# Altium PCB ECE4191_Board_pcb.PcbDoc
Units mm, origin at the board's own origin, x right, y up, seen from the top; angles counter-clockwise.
Board outline 150 x 61 mm, 2 copper layers (Top Layer, Bottom Layer), stack 1.65 mm thick; 23 components, 41 nets, 136 pads, 41 vias.
Unrouted connection lines stored in the file: 1.
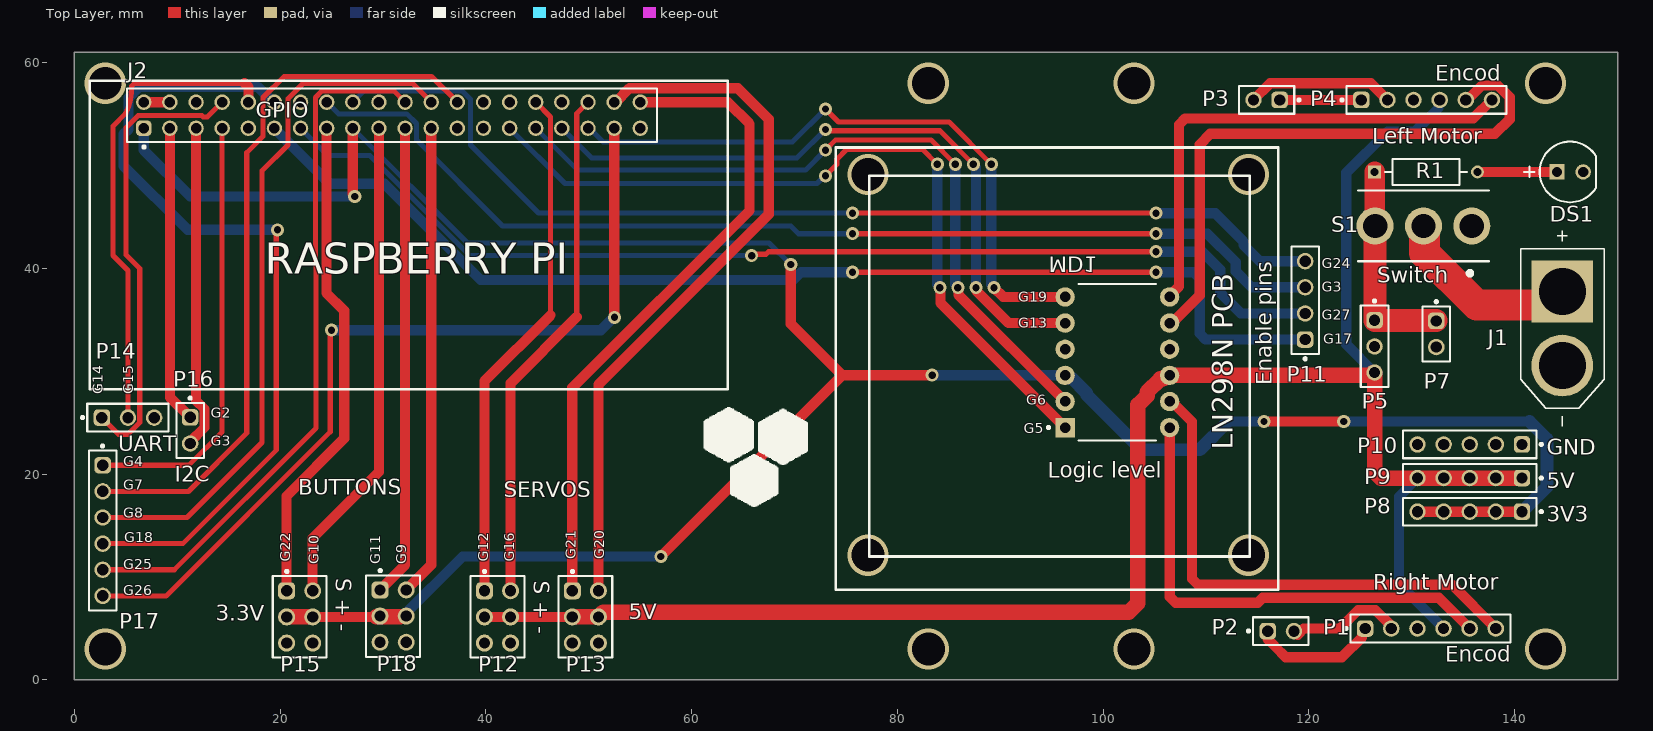
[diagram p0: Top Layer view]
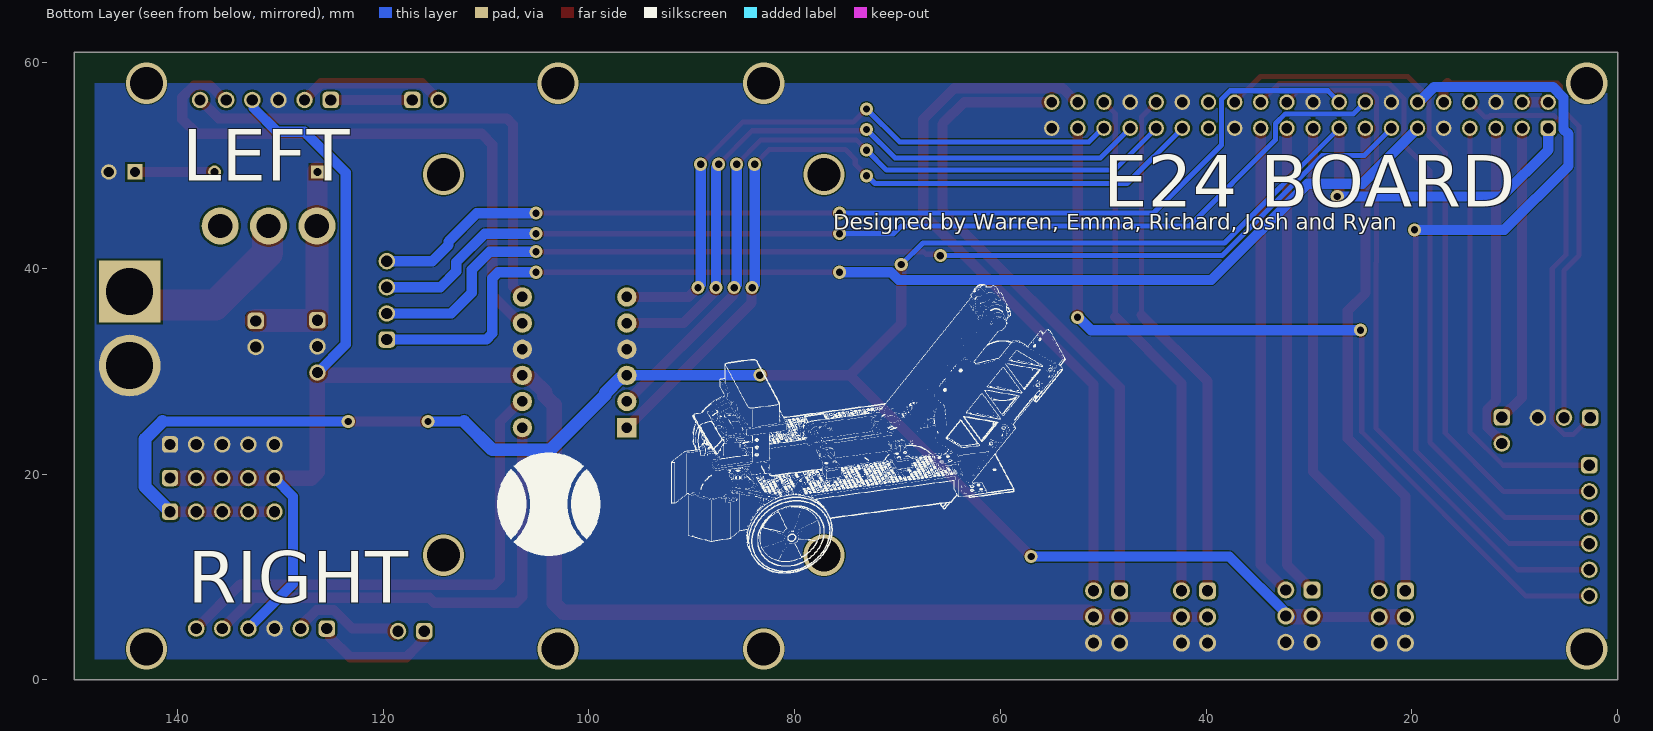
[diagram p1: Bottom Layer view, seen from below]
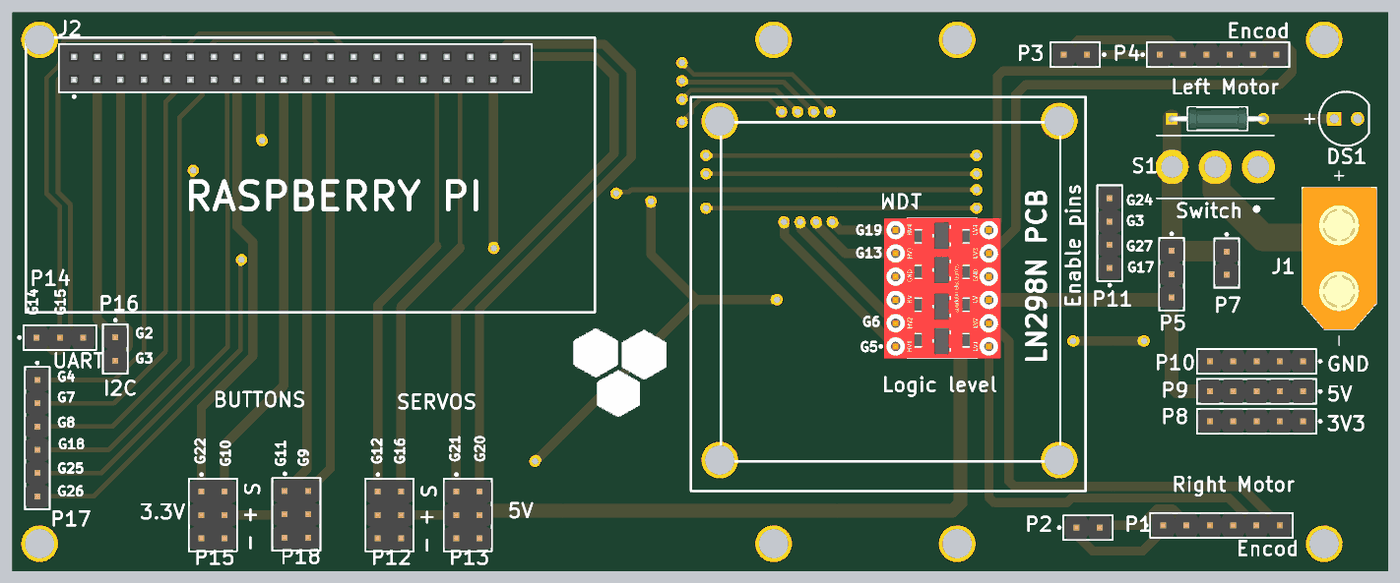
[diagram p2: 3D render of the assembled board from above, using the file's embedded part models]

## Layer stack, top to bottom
Top Solder: solder mask 0.0127, Solder Resist, Dk 3.8
Top Layer: signal copper 0.075
Dielectric: core 1.5, FR-4, Dk 4.5
Bottom Layer: signal copper 0.075
Bottom Solder: solder mask 0.0127, Solder Resist, Dk 3.8

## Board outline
0,0 0,61 150,61 150,0

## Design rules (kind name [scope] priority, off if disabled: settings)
BoardOutlineClearance [All] p1: gap=0.2 ignorepadtopadclearanceinfootprint=FALSE
Clearance [All] p1: gap=0.1 ignorepadtopadclearanceinfootprint=FALSE except(0.2: Arc-Arc Arc-Track Track-Track THPad-Fill THPad-Poly THPad-Region; 0.5: Arc-SMDPad Arc-Text Track-SMDPad Track-Text SMDPad-SMDPad SMDPad-THPad SMDPad-Via SMDPad-Fill SMDPad-Poly SMDPad-Region SMDPad-Text SMDPad-Hole THPad-THPad THPad-Via THPad-Text THPad-Hole Via-Text Fill-Text Poly-Text Region-Text Text-Text Text-Hole)
ComponentClearance [All] p1: gap=0.127 collisioncheckmode=3 verticalgap=0.127 showdistances=TRUE
DiffPairsRouting [All] p1: maxlimit=0.254 minlimit=0.127 mostfreqgap=0.127 toplayer_minwidth=0.127 toplayer_maxwidth=25.4 toplayer_prefwidth=0.127 bottomlayer_minwidth=0.127 bottomlayer_maxwidth=25.4 bottomlayer_prefwidth=0.127 maxuncoupledlength=12.7
Height [All] p1: minheight=0 maxheight=1816.048 prefheight=12.7
HoleSize [All] p1: absolutevalues=TRUE maxlimit=6.3 minlimit=0.3 maxpercent=80.000 minpercent=20.000
HoleToHoleClearance [All] p1: gap=0.25 allowstackedmicrovias=FALSE
MinimumAnnularRing [All] p1: minimumring=0.076
MinimumSolderMaskSliver [All] p1: minsoldermaskwidth=0
PlaneClearance [All] p1: clearance=0.127
PlaneConnect PlaneConnectPowerPads [InPadClass('PowerPads')] p1: planeconnectstyle=Direct reliefexpansion=0.508 reliefentries=4 reliefconductorwidth=0.254 reliefairgap=0.254
PlaneConnect [All] p2: pad.planeconnectstyle=Relief pad.reliefexpansion=0.3 pad.reliefentries=4 pad.reliefconductorwidth=0.127 pad.reliefairgap=0.127 via.planeconnectstyle=Direct via.reliefexpansion=0.3 via.reliefentries=4 via.reliefconductorwidth=0.127 via.reliefairgap=0.127
PolygonConnect PolygonConnectPowerPads [All vs (InPadClass('PowerPads'))] p1: connectstyle=Direct reliefconductorwidth=0.254 reliefentries=4 polygonreliefangle="90 Angle" airgapwidth=0.254
PolygonConnect [All] p2: thpad.connectstyle=Direct thpad.reliefconductorwidth=0.127 thpad.reliefentries=4 thpad.polygonreliefangle="90 Angle" thpad.airgapwidth=0.127 smdpad.connectstyle=Relief smdpad.reliefconductorwidth=0.127 smdpad.reliefentries=4 smdpad.polygonreliefangle="90 Angle" smdpad.airgapwidth=0.127 via.connectstyle=Direct via.reliefconductorwidth=0.127 via.reliefentries=4 via.polygonreliefangle="90 Angle" via.airgapwidth=0.127
RoutingVias [All] p1: holewidth=0.3 width=0.6 viastyle="Through Hole" minholewidth=0.3 minwidth=0.6 maxholewidth=0.6 maxwidth=6.6
SilkToSilkClearance [All] p1: silktosilkclearance=0
SilkToSolderMaskClearance [IsPad] p1: minsilkscreentomaskgap=0.127 clearancetoexposedcopper=TRUE
SolderMaskExpansion [All] p1: expansion=0.075 istentingtop=FALSE
Width [All] p1: maxlimit=25.4 minlimit=0.1 preferedwidth=1 minimp=50.000000 maximp=50.000000 favimp=50.000000
20 further rules are at their usual default settings.

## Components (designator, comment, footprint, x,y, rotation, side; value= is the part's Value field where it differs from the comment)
DS1 "UR502DC" CGX-UR502DC 145.377,49.377 r0 top
J1 "XT60-M" AMASS_XT60-M 144.627,34.155 r270 top
J2 "GPIO" 61304021821 30.875,54.895 r0 top
MD1 "BOB-12009" FP-BOB-12009-MFG 101.377,30.877 r0 top
P1 "Motor L" 61300611121 131.81,5 r0 top
P2 "LMotor Drive" 61300211121 117.27,4.75 r0 top
P3 "RMotor Drive" 61300211121 115.877,56.377 r180 top
P4 "Motor R" 61300611121 131.437,56.377 r0 top
P5 "LN298N" 61300311121 126.377,32.417 r270 top
P7 "To buck convter" 61300211121 132.377,33.627 r270 top
P8 "3.3V rail" 61300511121 135.627,16.36 r180 top
P9 "5V rail" 61300511121 135.627,19.627 r180 top
P10 "GND rail" 61300511121 135.627,22.894 r180 top
P11 "Motor enable pins" 61300411121 119.627,36.897 r90 top
P12 "61300621121" 61300621121 41.127,6.127 r270 top
P13 "61300621121" 61300621121 49.668,6.127 r270 top
P14 "UART" 61300311121 5.21,25.5 r0 top
P15 "61300621121" 61300621121 21.897,6.127 r270 top
P16 "I2C" 61300211121 11.25,24.25 r270 top
P17 "Spare pins" 61300611121 2.75,14.52 r270 top
P18 "61300621121" 61300621121 30.98,6.21 r270 top
R1 "1K" FP-MRS25-MFG 131.377,49.377 r0 top
S1 "Power Switch" 1MS1T1B1M1QES-1 131.127,44.127 r90 top

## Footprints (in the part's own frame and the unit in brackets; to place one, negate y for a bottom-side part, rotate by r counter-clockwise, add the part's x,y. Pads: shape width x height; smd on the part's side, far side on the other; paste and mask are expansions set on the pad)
1MS1T1B1M1QES-1 [mm]
  round 3.6 hole 2.37: 1(0,-4.7) 2(0,0) 3(0,4.7)
  silkscreen extent -4.76,-6.35 3.43,6.35
61300211121 [mm] "Pin Header, pitch 2.54 mm, THT, Vertical, single row, 2p"
  rrect50% 1.6x1.6 hole 1.1: 1(-1.27,0)
  round 1.6 hole 1.1: 2(1.27,0)
  silkscreen extent -3.26,-1.35 2.69,1.35, body extent -2.54,-1.27 2.54,1.27, height 8.57
61300311121 [mm] "Pin Header, pitch 2.54 mm, THT, Vertical, single row, 3p"
  rrect50% 1.6x1.6 hole 1.1: 1(-2.54,0)
  round 1.6 hole 1.1: 2(0,0) 3(2.54,0)
  silkscreen extent -4.53,-1.35 3.96,1.35, body extent -3.81,-1.27 3.81,1.27, height 8.57
61300411121 [mm] "Pin Header, pitch 2.54 mm, THT, Vertical, single row, 4p"
  rrect50% 1.6x1.6 hole 1.1: 1(-3.81,0)
  round 1.6 hole 1.1: 2(-1.27,0) 3(1.27,0) 4(3.81,0)
  silkscreen extent -5.8,-1.35 5.23,1.35, body extent -5.08,-1.27 5.08,1.27, height 8.57
61300511121 [mm] "Pin Header, pitch 2.54 mm, THT, Vertical, single row, 5p"
  rrect50% 1.6x1.6 hole 1.1: 1(-5.08,0)
  round 1.6 hole 1.1: 2(-2.54,0) 3(0,0) 4(2.54,0) 5(5.08,0)
  silkscreen extent -7.07,-1.35 6.5,1.35, body extent -6.35,-1.27 6.35,1.27, height 8.57
61300611121 [mm] "Pin Header, pitch 2.54 mm, THT, Vertical, single row, 6p"
  rrect50% 1.6x1.6 hole 1.1: 1(-6.35,0)
  round 1.6 hole 1.1: 2(-3.81,0) 3(-1.27,0) 4(1.27,0) 5(3.81,0) 6(6.35,0)
  silkscreen extent -8.34,-1.35 7.77,1.35, body extent -7.62,-1.27 7.62,1.27, height 8.57
61300621121 [mm] "Pin Header, pitch 2.54 mm, THT, Vertical, dual row, 6p"
  rrect50% 1.65x1.65 hole 1.1: 1(-2.54,-1.27)
  round 1.65 hole 1.1: 2(-2.54,1.27) 3(0,-1.27) 4(0,1.27) 5(2.54,-1.27) 6(2.54,1.27)
  silkscreen extent -4.54,-2.62 3.96,2.62, body extent -3.81,-2.54 3.81,2.54, height 8.59
61304021821 [mm] "Socket Header, Pitch 2.54 mm, THT, Vertical, dual row, 40p"
  rrect50% 1.5x1.5 hole 1.02: 1(-24.13,-1.27)
  round 1.5 hole 1.02: 2(-24.13,1.27) 3(-21.59,-1.27) 4(-21.59,1.27) 5(-19.05,-1.27) 6(-19.05,1.27) 7(-16.51,-1.27) 8(-16.51,1.27) 9(-13.97,-1.27) 10(-13.97,1.27) 11(-11.43,-1.27) 12(-11.43,1.27) 13(-8.89,-1.27) 14(-8.89,1.27) 15(-6.35,-1.27) 16(-6.35,1.27) 17(-3.81,-1.27) 18(-3.81,1.27) 19(-1.27,-1.27) 20(-1.27,1.27) 21(1.27,-1.27) 22(1.27,1.27) 23(3.81,-1.27) 24(3.81,1.27) 25(6.35,-1.27) 26(6.35,1.27) 27(8.89,-1.27) 28(8.89,1.27) 29(11.43,-1.27) 30(11.43,1.27) 31(13.97,-1.27) 32(13.97,1.27) 33(16.51,-1.27) 34(16.51,1.27) 35(19.05,-1.27) 36(19.05,1.27) 37(21.59,-1.27) 38(21.59,1.27) 39(24.13,-1.27) 40(24.13,1.27)
  silkscreen extent -25.78,-3.22 25.78,2.62, body extent -25.65,-2.54 25.65,2.54, height 8.45
AMASS_XT60-M [mm]
  round 6 hole 4.55: N(3.6,0)
  rect 6x6 / inner round 6 / far side rect 6x6 hole 4.55: P(-3.6,0)
  silkscreen extent -9.5,-4.05 9.5,4.05, body extent -7.75,-4.05 7.75,4.05, height 16
CGX-UR502DC [mm] "THD, 2-Leads, Dia 5.9mm, Pin Spacing 2.54mm"
  rect 1.5x1.5 hole 1: 1(-1.27,0)
  round 1.5 hole 1: 2(1.27,0)
  silkscreen extent -4.47,-2.95 2.5,2.95, body extent -2.95,-2.95 2.5,2.95, height 9.1
FP-BOB-12009-MFG [mm]
  rect 1.88x1.88 hole 1.02 paste-2539.97 mask+0: 1(-5.08,-6.35)
  round 1.88 hole 1.02 paste-2539.97 mask+0: 2(-5.08,-3.81) 3(-5.08,-1.27) 4(-5.08,1.27) 5(-5.08,3.81) 6(-5.08,6.35) 7(5.08,6.35) 8(5.08,3.81) 9(5.08,1.27) 10(5.08,-1.27) 11(5.08,-3.81) 12(5.08,-6.35)
  silkscreen extent -6.82,-7.62 3.76,7.62, body extent -6.35,-7.62 6.35,7.62, height 5.34
FP-MRS25-MFG [mm]
  rect 1.25x1.25 hole 0.75 paste-2539.97 mask+0: 1(-5,0)
  round 1.25 hole 0.75 paste-2539.97 mask+0: 2(5,0)
  silkscreen extent -3.98,-1.25 3.98,1.25, body extent -5.72,-1.35 5.72,1.35, height 0.25

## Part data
DS1: library part CMP-007-00009-1, "Red LED, 80 mW, 30 mA, -25 to 85 degC, 2-Pin THD", Manufacturer="Shenzhen CGX", Package Description="2-Pin Through Hole Device, Dia 5.9 mm, Height 9.1 mm", Power=80mW
J1: "Plug; DC supply; XT60; male; PIN: 2; for cable; soldered; 30A; 500V", Package=Package
J2: library part CMP-1502-01370-3, Contact Resistance=20mΩ, Current Rating=3A, Operating Supply Voltage=250V
MD1: library part CMP-157458-000001-1, "LOGIC LEVEL CONVERTER - BI-DIREC"
P1 P4 P17: library part CMP-1502-01070-3, Color=Black, Contact Resistance=20mΩ, Current Rating=3A, Max Operating Temperature=105°C, Min Operating Temperature=-40°C, Operating Supply Voltage=250V
P2 P3 P7 P16: library part CMP-1712-00002-6, Color=Black, Contact Resistance=20mΩ, Current Rating=3A, Max Operating Temperature=125°C, Min Operating Temperature=-40°C, Operating Supply Voltage=250V
P5 P14: library part CMP-1502-01062-3, Color=Black, Contact Resistance=20mΩ, Current Rating=3A, Max Operating Temperature=105°C, Min Operating Temperature=-40°C, Operating Supply Voltage=250V
P8 P9 P10: library part CMP-1502-01068-3, Color=Black, Contact Resistance=20mΩ, Current Rating=3A, Max Operating Temperature=105°C, Min Operating Temperature=-40°C, Operating Supply Voltage=250V
P11: library part CMP-1502-01064-3, Color=Black, Contact Resistance=20mΩ, Current Rating=3A, Max Operating Temperature=105°C, Min Operating Temperature=-40°C, Operating Supply Voltage=250V
P12 P13 P15 P18: library part CMP-1502-01072-3, Color=Black, Contact Resistance=20mΩ, Current Rating=3A, Max Operating Temperature=105°C, Min Operating Temperature=-40°C, Operating Supply Voltage=250V
R1: library part CMP-00030-42632392-1, "1K resistor", Case/Package=Conformal, Max Operating Temperature=155°C, Max Power Dissipation=600mW, Min Operating Temperature=-55°C, Resistance=10kΩ, Temperature Coefficient=50ppm/°C, Tolerance=1%, Voltage Rating=350V
S1: library part 1MS1T1B1M1QES-1, "Switch", Manufacturer_Name="RS Pro"

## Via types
v1: diameter 1.27, hole 0.711, Top Layer to Bottom Layer, 29 vias
v2: diameter 4, hole 3.2, Top Layer to Bottom Layer, 12 vias

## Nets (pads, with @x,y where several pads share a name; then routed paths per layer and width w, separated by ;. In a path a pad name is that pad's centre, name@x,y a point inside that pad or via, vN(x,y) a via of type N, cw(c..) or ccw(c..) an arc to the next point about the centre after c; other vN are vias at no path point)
3.3V: J2.1 J2.17 MD1.3 P8.1 P8.2 P8.3 P8.4 P8.5 P15.3 P15.4 P18.3 P18.4 | length 247.5
  Top Layer w1: J2.1@6.62,53.5 J2.1 J2.1@6.87,53.75 ; P15.4 P18.3@29.337,6.127 ; J2.17 27.065,47.258 27.25,47.073 v1(27.25,47) ; v1(57,12) 74.627,29.627 ; v1@69.627,40.304 69.627,34.627 74.627,29.627 ; v1(83.377,29.627) 74.627,29.627 ; v1(115.627,25.127) v1(123.377,25.127) ; P8.5 P8.4 P8.3 P8.2 P8.1
  Top Layer w1.5: P15.3@20.587,6.127 P15.3 P15.4@23.127,6.127 ; P18.3@29.337,6.127 P18.4@31.667,6.127
  Bottom Layer w0.5: J2.17 38.213,42.477 67.527,42.477 v1(69.627,40.377)
  Bottom Layer w1: J2.1 6.745,51.505 11.25,47 v1(27.25,47) ; P18.4@31.877,6.127 37.75,12 v1(57,12) ; v1(83.377,29.627) 83.397,29.607 MD1.3 ; 112.127,25.127 v1(115.627,25.127) ; v1(123.377,25.127) 141.431,25.127
  Bottom Layer w1.25: MD1.3 96.467,29.607 96.782,29.292 96.992,29.292 98.362,27.922 98.362,27.746 103.731,22.377 109.377,22.377 112.127,25.127 ; P8.1 143.127,18.78 143.127,23.431 141.431,25.127
"12V original": J1.P S1.2 | length 18.7
  Top Layer w3: S1.2 131.242,44.012 131.242,41.512 136.308,36.446 143.318,36.446 J1.P
+5: MD1.10 P1.4 P4.4 P5.3 P9.1 P9.2 P9.3 P9.4 P9.5 P12.3 P12.4 P13.3 P13.4 | length 182.2
  Top Layer w1: P12.3 P12.4 P13.3
  Top Layer w1.5: P13.3 P13.4 51.403,6.592 102.498,6.592 103.377,7.471 103.377,26.731 104.267,27.621 104.267,27.974 105.55,29.257 105.838,29.257 105.998,29.417 106.164,29.417 106.354,29.607 125.945,29.607 126.215,29.877 P5.3 126.377,20.213 126.963,19.627 P9.5 P9.4 P9.3 P9.2 P9.1
  Bottom Layer w1: P5.3 126.371,29.877 123.627,32.621 123.627,49.291 127.633,53.297 130.297,53.297 132.592,55.592 132.592,56.262 P4.4 ; P9.5 128.747,17.827 128.747,9.333 P1.4 P1.4@133.08,5.006
+12: P5.1 P7.1 R1.1 S1.3 | length 20.5
  Top Layer w2: R1.1 126.402,49.352 126.402,44.152 S1.3 S1.3@126.402,44.102 ; P5.1@126.402,34.982 P5.1 P5.1@126.407,34.927 ; P7.1@132.347,34.927 P7.1
  Top Layer w2.25: P5.1@126.402,34.982 S1.3@126.402,44.102 ; P5.1@126.407,34.927 P7.1@132.347,34.927
GND: DS1.2 J1.N J2.6 J2.9 J2.14 J2.20 J2.25 J2.30 J2.34 J2.39 MD1.4 MD1.9 P1.3 P4.3 P5.2 P7.2 P10.1 P10.2 P10.3 P10.4 P10.5 P12.5 P12.6 P13.5 P13.6 P14.3 P15.5 P15.6 P18.5 P18.6
GPIO22: J2.15 P15.1 | length 48
  Top Layer w1: P15.1 20.627,17.877 26.235,23.485 26.235,35.875 24.5,37.61 24.5,53.6 J2.15
"GPIO 2 (SDA)": J2.3 P16.1 | length 28.9
  Top Layer w1: J2.3 9.285,27.485 P16.1
"GPIO 3 (SCL)": J2.5 P16.2 | length 31.6
  Top Layer w1: P16.2 11.25,23.142 12.65,24.542 12.65,26.334 11.825,27.159 J2.5
"GPIO 4": J2.7 P17.1 | length 42.5
  Top Layer w0.5: P17.1 11.12,20.87 14.365,24.115 J2.7
"GPIO 5": J2.29 MD1.1 | length 76.8
  Top Layer w0.5: v1(73,49) 74.099,50.099 74.099,50.599 75.05,51.55 82.454,51.55 v1(83.877,50.127)
  Top Layer w1: v1(84.127,38.127) 84.179,38.075 84.179,36.645 MD1.1
  Bottom Layer w0.5: J2.29 47.68,48.25 72.177,48.25 72.927,49 v1(73,49)
  Bottom Layer w1: v1(83.877,50.127) 83.877,38.45 84.127,38.2 v1(84.127,38.127)
"GPIO 6": J2.31 MD1.2 | length 72.2
  Top Layer w0.5: v1(73,51.5) 74,52.5 83.254,52.5 v1(85.627,50.127)
  Top Layer w1: v1(85.877,38.127) 85.929,38.075 85.929,37.435 MD1.2
  Bottom Layer w0.5: J2.31 48.92,49.55 71.05,49.55 v1(73,51.5)
  Bottom Layer w1: v1(85.627,50.127) 85.627,38.45 85.877,38.2 v1(85.877,38.127)
"GPIO 7": J2.26 P17.2 | length 70.4
  Top Layer w0.5: P17.2 11.08,18.33 16.75,24 16.75,51.25 18.345,52.845 18.345,56.621 20.389,58.665 34.725,58.665 J2.26
"GPIO 8": J2.24 P17.3 | length 68.3
  Top Layer w0.5: P17.3 10.96,15.79 18.25,23.08 18.25,49.5 20.75,52 20.75,56.486 22.229,57.965 32.885,57.965 J2.24
"GPIO 9 (MISO)": J2.21 P18.1 | length 45.9
  Top Layer w1: P18.1 32.145,11.185 J2.21
"GPIO 10(MOSI)": J2.19 P15.2 | length 47.6
  Top Layer w1: P15.2 23.167,8.947 23.147,8.967 23.147,13.78 29.605,20.238 J2.19
"GPIO 11": J2.23 P18.2 | length 45.9
  Top Layer w1: P18.2 34.685,11.185 J2.23
"GPIO 12": J2.32 P12.1 | length 50.8
  Top Layer w0.5: J2.32 46.285,54.725 46.285,35.465
  Top Layer w1: P12.1 39.857,29.037 46.285,35.465
"GPIO 13": J2.33 MD1.5 | length 66.1
  Top Layer w0.5: v1(73,53.5) 73.123,53.377 84.127,53.377 v1(87.377,50.127)
  Top Layer w1: v1(87.627,38.127) 87.679,38.075 87.679,37.825 90.817,34.687 MD1.5
  Bottom Layer w0.5: J2.33 50.26,50.75 70.25,50.75 v1(73,53.5)
  Bottom Layer w1: v1(87.377,50.127) 87.377,50.054 87.627,49.804 v1(87.627,38.127)
"GPIO 14 (TXD)": J2.8 P14.1 | length 44.7
  Top Layer w0.5: P14.1 4.31,23.86 5.197,23.86 6.36,25.024 6.36,39.987 5.017,41.33 5.017,53.672 6.195,54.85 12.406,54.85 12.521,54.735 12.935,54.735 J2.8@14.49,56.29
"GPIO 15 (RXD)": J2.10 P14.2 | length 46.4
  Top Layer w0.5: P14.2 5.21,39.79 3.75,41.25 3.75,53.827 5,55.077 ccw(c-0.183,57.537) 5.5,56.75 ccw(c0.619,57.426) 5.547,57.426 5.547,57.707 5.839,58 16.539,58
  Top Layer w1: 16.539,58 16.934,57.604 16.934,56.386 J2.10@17.03,56.29
"GPIO 16": J2.36 P12.2 | length 50.6
  Top Layer w0.5: 48.825,35.288 48.825,55.065 J2.36
  Top Layer w1: P12.2 42.397,28.86 48.825,35.288
"GPIO 17": J2.11 P11.1 | length 112.5
  Top Layer w0.5: v1(75.627,39.627) v1(105.127,39.627)
  Bottom Layer w1: J2.11 24.835,48.235 30.122,48.235 39.48,38.877 69.874,38.877 70.624,39.627 v1(75.627,39.627) ; v1(105.127,39.627) 108.791,39.627 109.377,39.041 109.377,33.673 109.963,33.087 P11.1
"GPIO 18": J2.12 P17.4 | length 81.7
  Top Layer w0.5: P17.4 10.54,13.25 19.627,22.337 19.627,43.627 v1(19.75,43.75)
  Bottom Layer w1: J2.12 19.31,56.165 17.835,57.64 6.311,57.64 5.265,56.594 5.265,53.541 4.767,53.043 4.767,49.99 11.007,43.75 v1(19.75,43.75)
"GPIO 19": J2.35 MD1.6 | length 62.7
  Top Layer w0.5: v1(73,55.5) 74.273,54.227 85.027,54.227 v1(89.127,50.127)
  Top Layer w1: v1(89.377,38.127) 90.277,37.227 MD1.6
  Bottom Layer w0.5: J2.35 50.06,53.625 51.41,52.275 69.775,52.275 v1(73,55.5)
  Bottom Layer w1: v1(89.127,50.127) 89.127,38.45 89.377,38.2 v1(89.377,38.127)
"GPIO 20": J2.38 P13.2 | length 69.5
  Top Layer w1: P13.2 50.938,28.688 67.5,45.25 67.5,54.5 64.485,57.515 53.95,57.515 52.6,56.165 J2.38
"GPIO 21": J2.40 P13.1 | length 64
  Top Layer w1: P13.1 48.398,28.398 65.627,45.627 65.627,54.046 63.508,56.165 J2.40
"GPIO 23": J2.16 P11.3 | length 104
  Top Layer w0.5: v1(75.627,43.377) v1(105.127,43.377)
  Bottom Layer w0.5: J2.16 25.663,55.027 32.298,55.027 33.25,54.076 33.25,52.5 41.623,44.127 69.627,44.127 70.377,43.377 v1(75.627,43.377)
  Bottom Layer w1: v1(105.127,43.377) 110.127,43.377 112.877,40.627 112.877,39.707 114.417,38.167 P11.3
"GPIO 24": J2.18 P11.4 | length 102.7
  Top Layer w0.5: v1(75.627,45.377) v1(105.127,45.377)
  Bottom Layer w0.5: J2.18 28.165,57.265 37.681,57.265 38.5,56.446 38.5,52 45.123,45.377 v1(75.627,45.377)
  Bottom Layer w1: v1(105.127,45.377) 110.877,45.377 113.627,42.627 113.627,42.293 115.213,40.707 P11.4
"GPIO 25": J2.22 P17.5 | length 68.1
  Top Layer w0.5: P17.5 9.71,10.71 23.5,24.5 23.5,40.523 23.425,40.598 23.425,56.621 24.069,57.265 31.045,57.265 J2.22
"GPIO 26": J2.37 P17.6 | length 85.1
  Top Layer w0.5: P17.6 8.92,8.17 24.875,24.125 24.875,33.875 v1(25,34)
  Top Layer w1: J2.37 52.483,53.608 52.483,35.267 v1(52.5,35.25)
  Bottom Layer w1: v1(25,34) 51.177,34 52.427,35.25 v1(52.5,35.25)
"GPIO 27": J2.13 P11.2 | length 106.7
  Top Layer w0.5: v1(65.835,41.242) 65.97,41.377 67.22,41.377 67.47,41.627 v1(105.127,41.627)
  Bottom Layer w0.5: J2.13 24.625,50.985 28.715,50.985 38.458,41.242 v1(65.835,41.242)
  Bottom Layer w1: v1(105.127,41.627) 109.627,41.627 111.377,39.877 111.377,37.627 113.377,35.627 P11.2
LEncoder1: MD1.12 P1.5 | length 47.3
  Top Layer w1: MD1.12 106.457,8.086 107.043,7.5 115.009,7.5 115.509,8 132.62,8 P1.5
LEncoder2: MD1.11 P1.6 | length 49.8
  Top Layer w1: MD1.11 106.661,27.067 108.627,25.101 108.627,9.836 109.213,9.25 133.91,9.25 P1.6
NetDS1_1: DS1.1 R1.2 | length 7.8
  Top Layer w1: R1.2 DS1.1 DS1.1@144.028,49.456
NetP1_1: P1.1 P2.1 | length 11.7
  Top Layer w1: P2.1@115.96,4 116.7,3.26 116.7,3.254 117.754,2.2 123.2,2.2 125.16,4.16 125.16,4.7 P1.1
NetP1_2: P1.2 P2.2 | length 11
  Top Layer w1: P2.2@118.895,4.395 119.5,5 123,5 124.8,6.8 126.44,6.8 127.885,5.355 127.885,5.115 P1.2
NetP3_1: P3.1 P4.1 | length 7.9
  Top Layer w1: P3.1 P4.1
NetP3_2: P3.2 P4.2 | length 14.4
  Top Layer w1: P3.2 116.23,58 126.004,58 P4.2
REncoder1: MD1.8 P4.5 | length 57.3
  Top Layer w1: MD1.8 106.661,34.687 109.377,37.403 109.377,52.041 110.413,53.077 138.077,53.077 139.509,54.509 139.509,56.635 138.367,57.777 136.809,57.777 135.409,56.377 P4.5
REncoder2: MD1.7 P4.6 | length 48.5
  Top Layer w1: MD1.7 106.457,37.333 107.377,38.253 107.377,53.991 107.963,54.577 135.987,54.577 P4.6
"RPI 5V": J2.2 J2.4 | length 2.5
  Top Layer w1: J2.2 J2.4
pads on no net: J2.27 J2.28 S1.1
copper on no net:
  other v2: 3,3 83,3 103,3 143,3 77.127,12.127 114.127,12.127 77.127,49.127 114.127,49.127 3,58 83,58 103,58 143,58

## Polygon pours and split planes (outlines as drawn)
GND on Bottom Layer "GND_L02_P000" (solid, pour order 0): 1,58 148,58 148,2 1,2

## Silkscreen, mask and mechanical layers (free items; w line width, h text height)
Top Overlay:
  drawing of 15 lines, arcs and shapes, not listed
  text "Encod" at 132.254,58.254 h1.52
  text "GPIO" at 17.631,54.631 h1.52
  text "Left Motor" at 126.131,52.131 h1.52
  text "G24" at 121.254,40.004 h1
  text "RASPBERRY PI" at 18.5,39.5 h3
  text "Switch" at 126.631,38.631 h1.52
  text "G3" at 121.254,37.754 h1
  text "G19" at 91.754,36.754 h1
  text "G27" at 121.254,35.004 h1
  text "G13" at 91.754,34.254 h1
  text "G17" at 121.381,32.701 h1
  text "Enable pins" at 116.365,28.631 h1.52 r90
  text "G14" at 2.746,27.754 h1 r90
  text "G15" at 5.746,27.754 h1 r90
  text "G6" at 92.504,26.754 h1
  text "G2" at 13.254,25.504 h1
  text "G5" at 92.254,24.004 h1
  text "G3" at 13.254,22.754 h1
  text "LN298N PCB" at 112.6,22.4 h2 r90
  text "UART" at 4.254,22.254 h1.52
  text "GND" at 143.131,21.881 h1.52
  text "G4" at 4.754,20.754 h1
  text "Logic level" at 94.631,19.639 h1.52
  text "I2C" at 9.754,19.254 h1.52
  text "5V" at 143.131,18.631 h1.52
  text "G7" at 4.754,18.504 h1
  text "BUTTONS" at 21.754,18.004 h1.52
  text "SERVOS" at 41.754,17.754 h1.52
  text "G8" at 4.754,15.754 h1
  text "3V3" at 143.131,15.381 h1.52
  text "G18" at 4.849,13.392 h1
  text "G21" at 48.746,11.754 h1 r90
  text "G20" at 51.496,11.754 h1 r90
  text "G22" at 20.996,11.504 h1 r90
  text "G12" at 40.246,11.504 h1 r90
  text "G16" at 42.746,11.504 h1 r90
  text "G10" at 23.746,11.254 h1 r90
  text "G11" at 29.746,11.254 h1 r90
  text "G9" at 32.246,11.254 h1 r90
  text "G25" at 4.754,10.754 h1
  text "S + -" at 25.381,9.873 h1.52 r270
  text "S + -" at 44.631,9.623 h1.52 r270
  text "Right Motor" at 126.254,8.762 h1.52
  text "G26" at 4.754,8.254 h1
  text "5V" at 53.881,5.881 h1.52
  text "3.3V" at 13.754,5.754 h1.52
  text "Encod" at 133.254,1.754 h1.52
Bottom Overlay:
  drawing of 698 lines, arcs and shapes, not listed
  text "LEFT" at 139.5,48.5 h5
  text "E24 BOARD" at 50,46 h5
  text "Designed by Warren, Emma, Richard, Josh and Ryan" at 76.246,43.762 h1.52
  text "RIGHT" at 139,7.5 h5
Mechanical 1:
  the board outline again, w0.254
